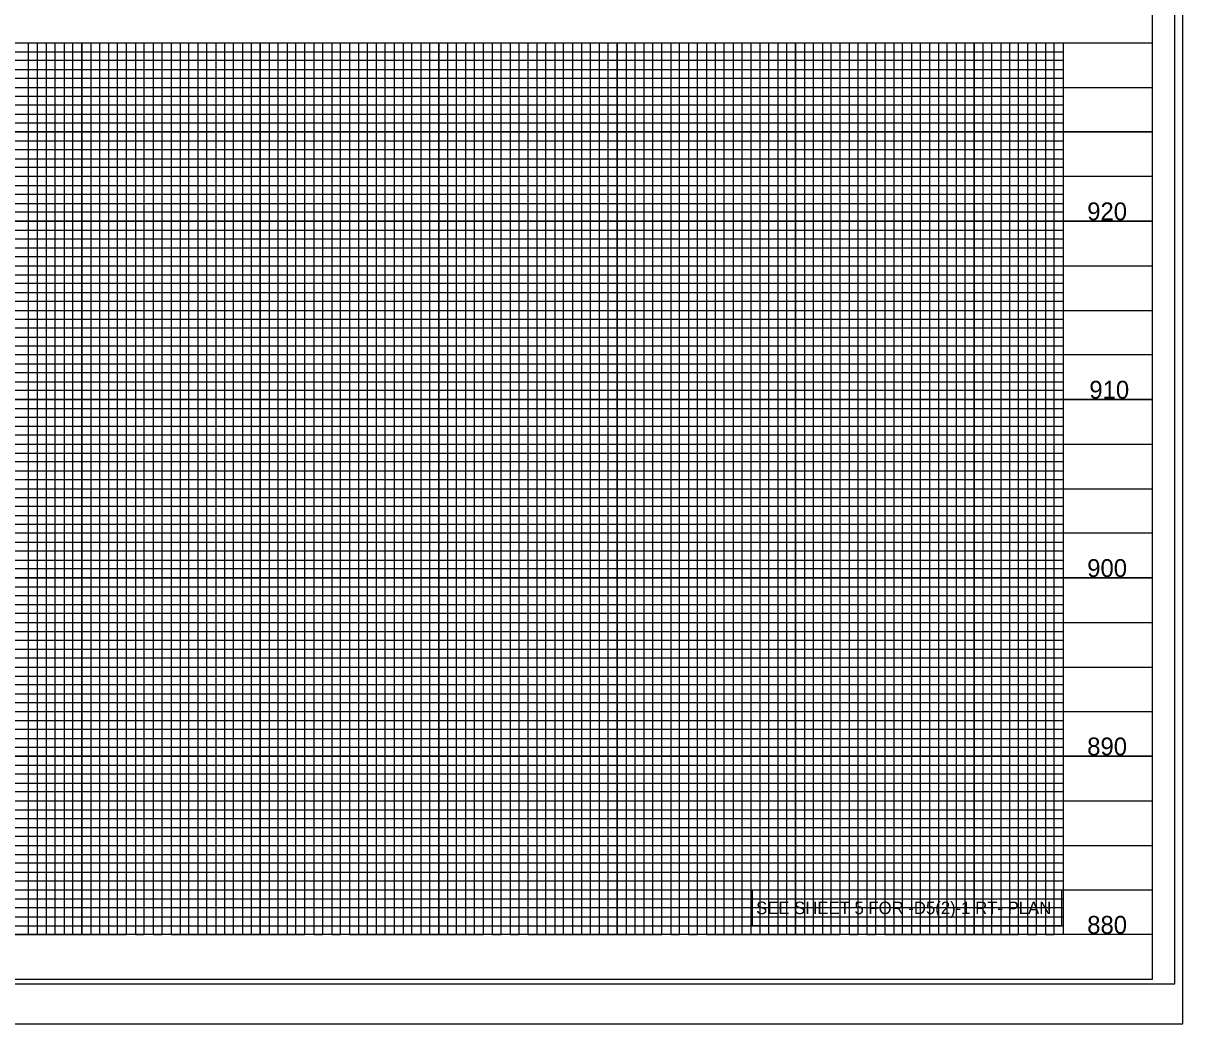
# Model space of a CAD drawing. Extents: x 1647943 to 1651624, y 802691 to 845761.
# Drawn here: x 1649896 to 1650546, y 802691 to 803252 of the extents above; entities that cross this region are included whole.
import ezdxf

# ---------------------------------------------------------------- set-up
doc = ezdxf.new("R2010")
doc.units = 0
for name, color, linetype in [('Exist Vertical Profile Vertical Axis Label', 7, 'Continuous'), ('Prop Dimension', 7, 'Continuous'), ('Prop Grid Mask', 7, 'Continuous'), ('Sheet Cutting Line CELL', 7, 'Continuous'), ('Sheet DOT Grid CELL', 7, 'Continuous'), ('Sheet Layout Profile Border Port 2', 7, 'Continuous'), ('Sheet Plot Border Inside CELL', 7, 'Continuous'), ('Sheet Plot Border Outside CELL', 7, 'Continuous'), ('Sheet Profile CELL', 7, 'Continuous'), ('Sheet Profile Grid Major CELL', 7, 'Continuous'), ('Sheet Profile Grid Middle CELL', 7, 'Continuous'), ('Sheet Profile Grid Minor CELL', 7, 'Continuous')]:
    doc.layers.add(name, color=color, linetype=linetype)

msp = doc.modelspace()

# ---------------------------------------------------------------- linework, layer by layer
at = {"layer": 'Prop Grid Mask'}
msp.add_lwpolyline([(1650304.96, 802766.02), (1650304.96, 802746.15), (1650478.56, 802746.15), (1650478.56, 802766.02)], close=True, dxfattribs=at)
at = {"layer": 'Sheet Cutting Line CELL'}
msp.add_line((1648862.28, 802691.02), (1650546.28, 802691.02), dxfattribs=at)
at = {"layer": 'Sheet DOT Grid CELL'}
for p, q in [((1649029.28, 803241.02), (1650529.17, 803241.02)), ((1649929.28, 803241.02), (1649929.28, 802741.02)), ((1649979.28, 803241.02), (1649979.28, 802741.02)), ((1650029.28, 803241.02), (1650029.28, 802741.02)), ((1650079.28, 803241.02), (1650079.28, 802741.02)), ((1650129.28, 803241.02), (1650129.28, 802741.02)), ((1650179.28, 803241.02), (1650179.28, 802741.02)), ((1650229.28, 803241.02), (1650229.28, 802741.02)), ((1650279.28, 803241.02), (1650279.28, 802741.02)), ((1650329.28, 803241.02), (1650329.28, 802741.02)), ((1650379.28, 803241.02), (1650379.28, 802741.02)), ((1650429.28, 803241.02), (1650429.28, 802741.02)), ((1650479.28, 803241.02), (1650479.28, 802741.02)), ((1649029.28, 803191.02), (1650529.17, 803191.02)), ((1649029.28, 803141.02), (1650529.17, 803141.02)), ((1649029.28, 803091.02), (1650529.17, 803091.02)), ((1649029.28, 803041.02), (1650529.17, 803041.02)), ((1649029.28, 802991.02), (1650529.17, 802991.02)), ((1649029.28, 802941.02), (1650529.17, 802941.02)), ((1649029.28, 802891.02), (1650529.17, 802891.02)), ((1649029.28, 802841.02), (1650529.17, 802841.02)), ((1649029.28, 802791.02), (1650529.17, 802791.02))]:
    msp.add_line(p, q, dxfattribs=at)
at = {"layer": 'Sheet Layout Profile Border Port 2'}
msp.add_lwpolyline([(1649079.28, 803241.02), (1650479.28, 803241.02), (1650479.28, 802741.02), (1649079.28, 802741.02)], close=True, dxfattribs=at)
at = {"layer": 'Sheet Plot Border Inside CELL'}
msp.add_lwpolyline([(1648875.28, 802713.47), (1650541.78, 802713.47), (1650541.78, 803768.57), (1648875.28, 803768.57)], close=True, dxfattribs=at)
at = {"layer": 'Sheet Plot Border Outside CELL'}
msp.add_lwpolyline([(1648862.28, 802691.02), (1650546.28, 802691.02), (1650546.28, 803791.02), (1648862.28, 803791.02)], close=True, dxfattribs=at)
at = {"layer": 'Sheet Profile CELL'}
for p, q in [((1649029.28, 803241.02), (1650529.28, 803241.02)), ((1650529.28, 802741.02), (1649029.28, 802741.02)), ((1649029.28, 802716.02), (1650529.28, 802716.02))]:
    msp.add_line(p, q, dxfattribs=at)
msp.add_lwpolyline([(1650529.28, 803766.02), (1649029.28, 803766.02), (1649029.28, 802716.02), (1650529.28, 802716.02)], close=True, dxfattribs=at)
at = {"layer": 'Sheet Profile Grid Major CELL'}
for p, q in [((1649929.28, 803241.02), (1649979.28, 803241.02)), ((1650029.28, 803241.02), (1650079.28, 803241.02)), ((1650129.28, 803241.02), (1650179.28, 803241.02)), ((1650229.28, 803241.02), (1650279.28, 803241.02)), ((1650329.28, 803241.02), (1650379.28, 803241.02)), ((1650429.28, 803241.02), (1650479.28, 803241.02)), ((1650429.28, 802741.02), (1650429.28, 802741.02))]:
    msp.add_line(p, q, dxfattribs=at)
for points in [[(1649879.28, 802741.02), (1649929.28, 802741.02), (1649929.28, 803241.02), (1649979.28, 803241.02), (1649979.28, 802741.02), (1650029.28, 802741.02), (1650029.28, 803241.02), (1650079.28, 803241.02), (1650079.28, 802741.02), (1650129.28, 802741.02), (1650129.28, 803241.02), (1650179.28, 803241.02), (1650179.28, 802741.02), (1650229.28, 802741.02), (1650229.28, 803241.02), (1650279.28, 803241.02), (1650279.28, 802741.02), (1650329.28, 802741.02), (1650329.28, 803241.02), (1650379.28, 803241.02), (1650379.28, 802741.02), (1650429.28, 802741.02), (1650429.28, 802741.02), (1650429.28, 803241.02), (1650479.28, 803241.02), (1650479.28, 802741.02)], [(1650529.28, 803191.02), (1649029.28, 803191.02)], [(1650529.28, 803141.02), (1649029.28, 803141.02), (1649029.28, 803091.02), (1650529.28, 803091.02)], [(1650529.28, 803041.02), (1649029.28, 803041.02), (1649029.28, 802991.02), (1650529.28, 802991.02)], [(1650529.28, 802941.02), (1649029.28, 802941.02), (1649029.28, 802891.02), (1650529.28, 802891.02)], [(1650529.28, 802841.02), (1649029.28, 802841.02), (1649029.28, 802841.02), (1649029.28, 802791.02), (1650529.28, 802791.02)], [(1650529.28, 802741.02), (1649029.28, 802741.02)]]:
    msp.add_lwpolyline(points, dxfattribs=at)
at = {"layer": 'Sheet Profile Grid Middle CELL'}
for points in [[(1649854.28, 803241.02), (1649904.28, 803241.02), (1649904.28, 802741.02), (1649954.28, 802741.02), (1649954.28, 803241.02), (1650004.28, 803241.02), (1650004.28, 802741.02), (1650054.28, 802741.02), (1650054.28, 803241.02), (1650104.28, 803241.02), (1650104.28, 802741.02), (1650154.28, 802741.02), (1650154.28, 803241.02), (1650204.28, 803241.02), (1650204.28, 802741.02), (1650254.28, 802741.02), (1650254.28, 803241.02), (1650304.28, 803241.02), (1650304.28, 802741.02), (1650354.28, 802741.02), (1650354.28, 803241.02), (1650404.28, 803241.02), (1650404.28, 802741.02), (1650454.28, 802741.02), (1650454.28, 803241.02)], [(1649029.28, 803216.02), (1650529.28, 803216.02)], [(1650529.28, 803166.02), (1649029.28, 803166.02), (1649029.28, 803116.02), (1650529.28, 803116.02)], [(1650529.28, 803066.02), (1649029.28, 803066.02), (1649029.28, 803016.02), (1650529.28, 803016.02)], [(1650529.28, 802966.02), (1649029.28, 802966.02), (1649029.28, 802916.02), (1650529.28, 802916.02)], [(1650529.28, 802866.02), (1649029.28, 802866.02), (1649029.28, 802816.02), (1650529.28, 802816.02)], [(1650529.28, 802766.02), (1649029.28, 802766.02)]]:
    msp.add_lwpolyline(points, dxfattribs=at)
at = {"layer": 'Sheet Profile Grid Minor CELL'}
for p, q in [((1649079.28, 803236.02), (1650479.28, 803236.02)), ((1650479.28, 803231.02), (1649079.28, 803231.02)), ((1649079.28, 803226.02), (1650479.28, 803226.02)), ((1650479.28, 803221.02), (1649079.28, 803221.02)), ((1649079.28, 803211.02), (1650479.28, 803211.02)), ((1650479.28, 803206.02), (1649079.28, 803206.02)), ((1649079.28, 803201.02), (1650479.28, 803201.02)), ((1650479.28, 803196.02), (1649079.28, 803196.02)), ((1649079.28, 803186.02), (1650479.28, 803186.02)), ((1650479.28, 803181.02), (1649079.28, 803181.02)), ((1649079.28, 803176.02), (1650479.28, 803176.02)), ((1650479.28, 803171.02), (1649079.28, 803171.02)), ((1649079.28, 803161.02), (1650479.28, 803161.02)), ((1650479.28, 803156.02), (1649079.28, 803156.02)), ((1649079.28, 803151.02), (1650479.28, 803151.02)), ((1650479.28, 803146.02), (1649079.28, 803146.02)), ((1649079.28, 803136.02), (1650479.28, 803136.02)), ((1650479.28, 803131.02), (1649079.28, 803131.02)), ((1649079.28, 803126.02), (1650479.28, 803126.02)), ((1650479.28, 803121.02), (1649079.28, 803121.02)), ((1649079.28, 803111.02), (1650479.28, 803111.02)), ((1650479.28, 803106.02), (1649079.28, 803106.02)), ((1649079.28, 803101.02), (1650479.28, 803101.02)), ((1650479.28, 803096.02), (1649079.28, 803096.02)), ((1649079.28, 803086.02), (1650479.28, 803086.02)), ((1650479.28, 803081.02), (1649079.28, 803081.02)), ((1649079.28, 803076.02), (1650479.28, 803076.02)), ((1650479.28, 803071.02), (1649079.28, 803071.02)), ((1649079.28, 803061.02), (1650479.28, 803061.02)), ((1650479.28, 803056.02), (1649079.28, 803056.02)), ((1649079.28, 803051.02), (1650479.28, 803051.02)), ((1650479.28, 803046.02), (1649079.28, 803046.17)), ((1649079.28, 803036.02), (1650479.28, 803036.02)), ((1650479.28, 803031.02), (1649079.28, 803031.02)), ((1649079.28, 803026.02), (1650479.28, 803026.02)), ((1650479.28, 803021.02), (1649079.28, 803021.02)), ((1649079.28, 803011.02), (1650479.28, 803011.02)), ((1650479.28, 803006.02), (1649079.28, 803006.02)), ((1649079.28, 803001.02), (1650479.28, 803001.02)), ((1650479.28, 802996.02), (1649079.28, 802996.02)), ((1649079.28, 802986.02), (1650479.28, 802986.02)), ((1650479.28, 802981.02), (1649079.28, 802981.02)), ((1649079.28, 802976.02), (1650479.28, 802976.02)), ((1650479.28, 802971.02), (1649079.28, 802971.02)), ((1649079.28, 802961.02), (1650479.28, 802961.02)), ((1650479.28, 802956.02), (1649079.28, 802956.02)), ((1649079.28, 802951.02), (1650479.28, 802951.02)), ((1650479.28, 802946.02), (1649079.28, 802946.02)), ((1649079.28, 802936.02), (1650479.28, 802936.02)), ((1650479.28, 802931.02), (1649079.28, 802931.02)), ((1649079.28, 802926.02), (1650479.28, 802926.02)), ((1650479.28, 802921.02), (1649079.28, 802921.02)), ((1649079.28, 802911.02), (1650479.28, 802911.02)), ((1650479.28, 802906.02), (1649079.28, 802906.02)), ((1649079.28, 802901.02), (1650479.28, 802901.02)), ((1650479.28, 802896.02), (1649079.28, 802896.02)), ((1649079.28, 802886.02), (1650479.28, 802886.02)), ((1650479.28, 802881.02), (1649079.28, 802881.02)), ((1649079.28, 802876.02), (1650479.28, 802876.02)), ((1650479.28, 802871.02), (1649079.28, 802871.02)), ((1649079.28, 802861.02), (1650479.28, 802861.02)), ((1650479.28, 802856.02), (1649079.28, 802856.02)), ((1649079.28, 802851.02), (1650479.28, 802851.02)), ((1650479.28, 802846.02), (1649079.28, 802846.02)), ((1649079.28, 802836.02), (1650479.28, 802836.02)), ((1650479.28, 802831.02), (1649079.28, 802831.02)), ((1649079.28, 802826.02), (1650479.28, 802826.02)), ((1650479.28, 802821.02), (1649079.28, 802821.02)), ((1649079.28, 802811.02), (1650479.28, 802811.02)), ((1650479.28, 802806.02), (1649079.28, 802806.02)), ((1649079.28, 802801.02), (1650479.28, 802801.02)), ((1650479.28, 802796.02), (1649079.28, 802796.02)), ((1649079.28, 802786.02), (1650479.28, 802786.02)), ((1650479.28, 802781.02), (1649079.28, 802781.02)), ((1649079.28, 802776.02), (1650479.28, 802776.02)), ((1650479.28, 802771.02), (1649079.28, 802771.02)), ((1649079.28, 802761.02), (1650479.28, 802761.02)), ((1650479.28, 802756.02), (1649079.28, 802756.02)), ((1649079.28, 802751.02), (1650479.28, 802751.02)), ((1649079.28, 802746.02), (1650479.28, 802746.02)), ((1650479.28, 802746.02), (1650479.28, 802746.02))]:
    msp.add_line(p, q, dxfattribs=at)
for points in [[(1649894.28, 802741.02), (1649899.28, 802741.02), (1649899.28, 803241.02), (1649909.28, 803241.02), (1649909.28, 802741.02), (1649914.28, 802741.02)], [(1649914.28, 802741.02), (1649914.28, 803241.02), (1649919.28, 803241.02), (1649919.28, 802741.02), (1649924.28, 802741.02), (1649924.28, 803241.02), (1649934.28, 803241.02), (1649934.28, 802741.02), (1649939.28, 802741.02), (1649939.28, 803241.02), (1649944.28, 803241.02), (1649944.28, 802741.02), (1649949.28, 802741.02), (1649949.28, 803241.02), (1649959.28, 803241.02), (1649959.28, 802741.02), (1649964.28, 802741.02), (1649964.28, 803241.02), (1649969.28, 803241.02), (1649969.28, 802741.02), (1649974.28, 802741.02), (1649974.28, 803241.02), (1649984.28, 803241.02), (1649984.28, 802741.02), (1649989.28, 802741.02), (1649989.28, 803241.02), (1649994.28, 803241.02), (1649994.28, 802741.02), (1649999.28, 802741.02), (1649999.28, 803241.02), (1650009.28, 803241.02), (1650009.28, 802741.02), (1650014.28, 802741.02), (1650014.28, 803241.02), (1650019.28, 803241.02), (1650019.28, 802741.02), (1650024.28, 802741.02), (1650024.28, 803241.02), (1650034.28, 803241.02), (1650034.28, 802741.02), (1650039.28, 802741.02), (1650039.28, 803241.02), (1650044.28, 803241.02), (1650044.28, 802741.02), (1650049.28, 802741.02), (1650049.28, 803241.02), (1650059.28, 803241.02), (1650059.28, 802741.02), (1650064.28, 802741.02), (1650064.28, 803241.02), (1650069.28, 803241.02), (1650069.28, 802741.02), (1650074.28, 802741.02), (1650074.28, 803241.02), (1650084.28, 803241.02), (1650084.28, 802741.02), (1650089.28, 802741.02), (1650089.28, 803241.02), (1650094.28, 803241.02), (1650094.28, 802741.02), (1650099.28, 802741.02), (1650099.28, 803241.02), (1650109.28, 803241.02), (1650109.28, 802741.02), (1650114.28, 802741.02), (1650114.28, 803241.02), (1650119.28, 803241.02), (1650119.28, 802741.02), (1650124.28, 802741.02), (1650124.28, 803241.02), (1650134.28, 803241.02), (1650134.28, 802741.02), (1650139.28, 802741.02), (1650139.28, 803241.02), (1650144.28, 803241.02), (1650144.28, 802741.02), (1650149.28, 802741.02), (1650149.28, 803241.02), (1650159.28, 803241.02), (1650159.28, 802741.02), (1650164.28, 802741.02), (1650164.28, 803241.02), (1650169.28, 803241.02), (1650169.28, 802741.02), (1650174.28, 802741.02), (1650174.28, 803241.02), (1650184.28, 803241.02), (1650184.28, 802741.02), (1650189.28, 802741.02), (1650189.28, 803241.02), (1650194.28, 803241.02), (1650194.28, 802741.02), (1650199.28, 802741.02), (1650199.28, 803241.02), (1650209.28, 803241.02), (1650209.28, 802741.02), (1650214.28, 802741.02), (1650214.28, 803241.02), (1650219.28, 803241.02), (1650219.28, 802741.02)], [(1650219.28, 802741.02), (1650224.28, 802741.02), (1650224.28, 803241.02), (1650234.28, 803241.02), (1650234.28, 802741.02), (1650239.28, 802741.02), (1650239.28, 803241.02), (1650244.28, 803241.02), (1650244.28, 802741.02), (1650249.28, 802741.02), (1650249.28, 803241.02), (1650259.28, 803241.02), (1650259.28, 802741.02), (1650264.28, 802741.02), (1650264.28, 803241.02), (1650269.28, 803241.02), (1650269.28, 802741.02), (1650274.28, 802741.02), (1650274.28, 803241.02), (1650284.28, 803241.02), (1650284.28, 802741.02), (1650289.28, 802741.02), (1650289.28, 803241.02), (1650294.28, 803241.02), (1650294.28, 802741.02), (1650299.28, 802741.02), (1650299.28, 803241.02), (1650309.28, 803241.02), (1650309.28, 802741.02), (1650314.28, 802741.02), (1650314.28, 803241.02), (1650319.28, 803241.02), (1650319.28, 802741.02), (1650324.28, 802741.02), (1650324.28, 803241.02), (1650334.28, 803241.02), (1650334.28, 802741.02), (1650339.28, 802741.02), (1650339.28, 803241.02), (1650344.28, 803241.02), (1650344.28, 802741.02), (1650349.28, 802741.02), (1650349.28, 803241.02), (1650359.28, 803241.02), (1650359.28, 802741.02), (1650364.28, 802741.02), (1650364.28, 803241.02), (1650369.28, 803241.02), (1650369.28, 802741.02), (1650374.28, 802741.02), (1650374.28, 803241.02), (1650384.28, 803241.02), (1650384.28, 802741.02), (1650389.28, 802741.02), (1650389.28, 803241.02), (1650394.28, 803241.02), (1650394.28, 802741.02), (1650399.28, 802741.02), (1650399.28, 803241.02), (1650409.28, 803241.02), (1650409.28, 802741.02), (1650414.28, 802741.02), (1650414.28, 803241.02), (1650419.28, 803241.02), (1650419.28, 802741.02), (1650424.28, 802741.02), (1650424.28, 803241.02), (1650434.28, 803241.02), (1650434.28, 802741.02), (1650439.28, 802741.02), (1650439.28, 803241.02), (1650444.28, 803241.02), (1650444.28, 802741.02), (1650449.28, 802741.02), (1650449.28, 803241.02), (1650459.28, 803241.02), (1650459.28, 802741.02), (1650464.28, 802741.02), (1650464.28, 803241.02), (1650469.28, 803241.02), (1650469.28, 802741.02), (1650474.28, 802741.02), (1650474.28, 803241.02), (1650479.28, 803241.02)]]:
    msp.add_lwpolyline(points, dxfattribs=at)

# ---------------------------------------------------------------- texts
at = {"layer": 'Exist Vertical Profile Vertical Axis Label'}
for s, p in [('920', (1650492.71, 803141.52)), ('910', (1650493.91, 803041.52)), ('900', (1650492.71, 802941.52)), ('890', (1650492.71, 802841.52)), ('880', (1650492.71, 802741.52))]:
    msp.add_text(s, height=10, dxfattribs=at).set_placement(p)
at = {"layer": 'Prop Dimension'}
msp.add_text('SEE SHEET 5 FOR -D5(2)-1 RT- PLAN', height=7, dxfattribs=at).set_placement((1650307.15, 802752.52))

doc.saveas('drawing.dxf')
